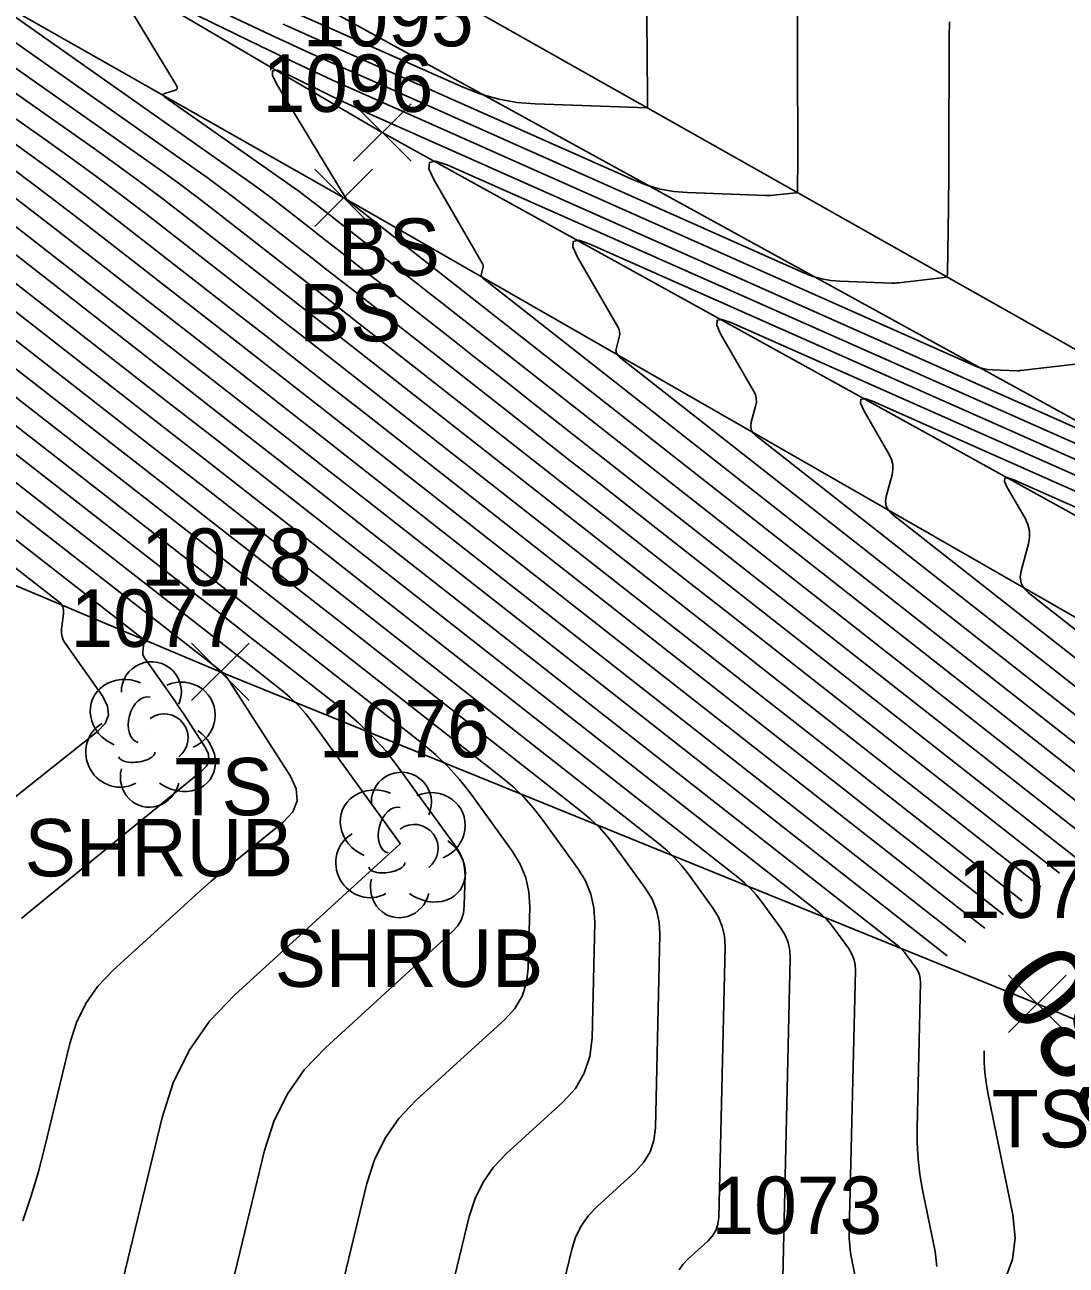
# Model space of a CAD drawing. Extents: x 1650836 to 1652450, y 332578 to 333908.
# Drawn here: x 1651878.29 to 1651914.59, y 332846.53 to 332889.77 of the extents above; entities that cross this region are included whole.
import ezdxf

# ---------------------------------------------------------------- set-up
doc = ezdxf.new("R2010")
doc.units = 0
for name, color, linetype in [('L_A', 7, 'Continuous'), ('L_I', 7, 'Continuous'), ('L_TIC', 7, 'Continuous'), ('LELB', 7, 'Continuous'), ('LSH', 7, 'Continuous'), ('LSOGCMA', 7, 'Continuous'), ('LSOGCMA_T', 7, 'Continuous'), ('LSOGCMI', 7, 'Continuous'), ('PET', 7, 'Continuous')]:
    doc.layers.add(name, color=color, linetype=linetype)

msp = doc.modelspace()

# ---------------------------------------------------------------- linework, layer by layer
at = {"layer": 'L_TIC'}
for points in [[(1651889.753, 332885.019), (1651891.753, 332887.019)], [(1651891.753, 332885.019), (1651889.753, 332887.019)], [(1651888.406, 332882.733), (1651890.406, 332884.733)], [(1651890.406, 332882.733), (1651888.406, 332884.733)], [(1651884.106, 332866.214), (1651886.106, 332868.214)], [(1651886.106, 332866.214), (1651884.106, 332868.214)], [(1651912.583, 332854.638), (1651914.583, 332856.638)], [(1651914.583, 332854.638), (1651912.583, 332856.638)]]:
    msp.add_lwpolyline(points, dxfattribs=at)
at = {"layer": 'LELB'}
for points in [[(1651844.759, 332915.941), (1651880.379, 332894.976), (1651917.082, 332874.787), (1651949.824, 332853.945), (1651967.074, 332844.342), (1652000.53, 332828.254), (1652035.357, 332809.776), (1652067.23, 332793.489), (1652106.029, 332773.108), (1652143.274, 332753.324), (1652172.167, 332734.049)], [(1652048.756, 332662.461), (1652082.555, 332678.298), (1652130.366, 332703.201), (1652148.083, 332715.406), (1652159.47, 332726.367), (1652148.02, 332734.227), (1652128.413, 332739.339), (1652116.951, 332747.33), (1652106.793, 332756.875), (1652094.604, 332761.138), (1652083.802, 332764.466), (1652074.482, 332770.284), (1652065.17, 332770.428), (1652062.989, 332774.387), (1652054.537, 332784.724), (1652034.993, 332796.475), (1652025.062, 332801.1), (1652009.772, 332808.074), (1651988.967, 332816.401), (1651980.006, 332832.954), (1651960.575, 332843.477), (1651932.852, 332862.75), (1651890.753, 332886.019), (1651847.527, 332911.35)], [(1651992.104, 332790.093), (1651989.915, 332804.738), (1651988.967, 332816.401), (1651977.078, 332830.976), (1651959.162, 332840.786), (1651931.328, 332859.703), (1651889.406, 332883.733), (1651845.231, 332908.813)], [(1651981.067, 332787.388), (1651974.596, 332810.786), (1651972.976, 332830.46), (1651956.891, 332837.411), (1651913.583, 332855.638), (1651885.106, 332867.214), (1651834.429, 332888.588)]]:
    msp.add_lwpolyline(points, dxfattribs=at)
at = {"layer": 'LSH'}
for p, q in [((1651882.657, 332865.085), (1651882.657, 332865.085)), ((1651882.657, 332865.085), (1651882.657, 332865.085)), ((1651891.371, 332861.234), (1651891.371, 332861.234)), ((1651891.371, 332861.234), (1651891.371, 332861.234))]:
    msp.add_line(p, q, dxfattribs=at)
for centre in [(1651882.704, 332866.519), (1651891.418, 332862.668)]:
    msp.add_arc(centre, 1.047, 335.5272, 180.9563, dxfattribs=at)
for centre, major_axis, ratio, start_param, end_param in [((1651881.865, 332865.752), (1.21, -0.512), 0.895232, 1.570796, 4.712389), ((1651883.698, 332865.669), (-1.141, -0.483), 0.949671, 1.570796, 4.712389), ((1651882.448, 332865.543), (-0.208, -0.792), 0.645439, 3.141593, 6.283185), ((1651883.157, 332864.919), (-0.5, 0.667), 0.989748, 3.141593, 6.283185), ((1651881.574, 332864.377), (0.584, -1.042), 0.959034, 3.141593, 6.283185), ((1651883.657, 332864.252), (-1.09, 0.792), 0.841452, 1.570796, 4.712389), ((1651882.199, 332864.335), (-0.625, -0.083), 0.423636, 0, 3.141593), ((1651882.657, 332863.585), (0.265, 1.061), 0.942809, 1.570796, 4.712389), ((1651890.58, 332861.9), (1.21, -0.512), 0.895232, 1.570796, 4.712389), ((1651892.413, 332861.817), (-1.141, -0.483), 0.949671, 1.570796, 4.712389), ((1651891.163, 332861.692), (-0.208, -0.792), 0.645439, 3.141593, 6.283185), ((1651891.871, 332861.067), (-0.5, 0.667), 0.989748, 3.141593, 6.283185), ((1651890.288, 332860.525), (0.584, -1.042), 0.959034, 3.141593, 6.283185), ((1651892.372, 332860.401), (-1.09, 0.792), 0.841452, 1.570796, 4.712389), ((1651890.913, 332860.484), (-0.625, -0.083), 0.423636, 0, 3.141593), ((1651891.372, 332859.734), (0.265, 1.061), 0.942809, 1.570796, 4.712389)]:
    msp.add_ellipse(centre, major_axis=major_axis, ratio=ratio, start_param=start_param, end_param=end_param, dxfattribs=at)
at = {"layer": 'LSOGCMA'}
for points in [[(1651911.748, 332858.275), (1651911.497, 332858.472), (1651910.953, 332858.899), (1651910.409, 332859.326), (1651909.864, 332859.754), (1651909.32, 332860.181), (1651890.123, 332875.244), (1651888.907, 332876.197), (1651887.691, 332877.149), (1651886.474, 332878.099), (1651885.256, 332879.049), (1651880.382, 332882.846), (1651879.158, 332883.788), (1651877.923, 332884.715), (1651876.676, 332885.627), (1651875.419, 332886.523), (1651848.21, 332905.675)], [(1651920.349, 332861.439), (1651899.012, 332878.194), (1651898.948, 332878.258), (1651898.91, 332878.331), (1651898.897, 332878.413), (1651898.91, 332878.503), (1651899.011, 332878.881), (1651899.028, 332878.974), (1651899.025, 332879.064), (1651899.004, 332879.152), (1651898.964, 332879.238), (1651897.554, 332881.671), (1651897.391, 332882.025), (1651897.406, 332882.22), (1651897.598, 332882.256), (1651897.967, 332882.132), (1651919.159, 332872.735)], [(1651868.932, 332881.845), (1651884.308, 332869.865), (1651884.927, 332869.383), (1651885.544, 332868.9), (1651886.162, 332868.417), (1651886.779, 332867.933), (1651889.418, 332865.863), (1651889.932, 332865.43), (1651890.412, 332864.965), (1651890.859, 332864.467), (1651891.271, 332863.937), (1651893.333, 332861.094), (1651893.47, 332860.871), (1651893.566, 332860.635), (1651893.621, 332860.386), (1651893.635, 332860.125), (1651893.61, 332859.055), (1651893.58, 332858.798), (1651893.501, 332858.564), (1651893.376, 332858.351), (1651893.202, 332858.159), (1651888.769, 332854.114), (1651888.033, 332853.339), (1651887.434, 332852.483), (1651886.972, 332851.546), (1651886.647, 332850.527), (1651883.641, 332838.089)]]:
    msp.add_lwpolyline(points, dxfattribs=at)
at = {"layer": 'LSOGCMI'}
for points in [[(1651845.912, 332905.525), (1651871.913, 332887.223), (1651873.486, 332886.101), (1651875.044, 332884.961), (1651876.589, 332883.802), (1651878.12, 332882.624), (1651884.215, 332877.875), (1651885.739, 332876.687), (1651887.261, 332875.498), (1651888.782, 332874.308), (1651890.302, 332873.116), (1651910.444, 332857.312)], [(1651847.061, 332905.6), (1651873.666, 332886.873), (1651875.081, 332885.864), (1651876.484, 332884.838), (1651877.874, 332883.795), (1651879.251, 332882.735), (1651884.735, 332878.462), (1651886.106, 332877.393), (1651887.476, 332876.323), (1651888.845, 332875.252), (1651890.213, 332874.18), (1651911.096, 332857.794)], [(1651912.399, 332858.755), (1651909.768, 332860.822), (1651908.772, 332861.604), (1651907.776, 332862.385), (1651906.781, 332863.167), (1651905.785, 332863.948), (1651890.033, 332876.308), (1651888.97, 332877.141), (1651887.906, 332877.974), (1651886.841, 332878.805), (1651885.776, 332879.636), (1651881.513, 332882.958), (1651880.442, 332883.781), (1651879.362, 332884.592), (1651878.272, 332885.389), (1651877.172, 332886.173), (1651849.359, 332905.751)], [(1651851.136, 332905.867), (1651851.012, 332905.705), (1651851.086, 332905.478), (1651851.378, 332905.214), (1651878.925, 332885.824), (1651879.867, 332885.152), (1651880.801, 332884.469), (1651881.727, 332883.774), (1651882.644, 332883.069), (1651886.296, 332880.223), (1651887.209, 332879.511), (1651888.121, 332878.799), (1651889.032, 332878.086), (1651889.943, 332877.372), (1651902.25, 332867.715), (1651903.697, 332866.58), (1651905.144, 332865.444), (1651906.591, 332864.308), (1651908.038, 332863.172), (1651913.05, 332859.236)], [(1651846.352, 332902.563), (1651866.654, 332888.272), (1651868.7, 332886.813), (1651870.727, 332885.33), (1651872.736, 332883.823), (1651874.727, 332882.291), (1651882.655, 332876.114), (1651884.636, 332874.569), (1651886.616, 332873.023), (1651888.595, 332871.474), (1651890.572, 332869.924), (1651903.158, 332860.049), (1651903.379, 332859.862), (1651903.587, 332859.662), (1651903.779, 332859.447), (1651903.957, 332859.218), (1651904.641, 332858.276), (1651904.789, 332858.033), (1651904.894, 332857.777), (1651904.953, 332857.507), (1651904.969, 332857.223), (1651904.684, 332845.065)], [(1651857.738, 332901.621), (1651880.678, 332885.474), (1651881.462, 332884.915), (1651882.24, 332884.346), (1651883.011, 332883.767), (1651883.775, 332883.18), (1651886.816, 332880.81), (1651887.576, 332880.218), (1651888.336, 332879.624), (1651889.095, 332879.03), (1651889.853, 332878.435), (1651898.968, 332871.284), (1651900.74, 332869.893), (1651902.512, 332868.503), (1651904.283, 332867.112), (1651906.055, 332865.721), (1651913.701, 332859.717)], [(1651914.352, 332860.197), (1651902.711, 332869.338), (1651901.295, 332870.45), (1651899.88, 332871.561), (1651898.464, 332872.673), (1651897.048, 332873.784), (1651889.763, 332879.499), (1651889.157, 332879.975), (1651888.55, 332880.449), (1651887.943, 332880.924), (1651887.336, 332881.397), (1651884.906, 332883.291), (1651884.295, 332883.761), (1651883.679, 332884.223), (1651883.058, 332884.677), (1651882.431, 332885.124), (1651864.098, 332898.029)], [(1651886.698, 332890.648), (1651893.59, 332887.584), (1651894.192, 332887.349), (1651894.808, 332887.175), (1651895.438, 332887.061), (1651896.082, 332887.008), (1651899.985, 332886.869), (1651899.99, 332886.869), (1651899.996, 332886.87), (1651899.997, 332886.871), (1651899.997, 332886.873), (1651899.997, 332886.965), (1651899.997, 332886.997), (1651899.997, 332887.028), (1651899.995, 332887.159), (1651899.994, 332887.213), (1651899.994, 332887.267), (1651899.925, 332895.585)], [(1651905.217, 332894.718), (1651905.219, 332889.324), (1651905.219, 332888.95), (1651905.22, 332888.576), (1651905.221, 332888.202), (1651905.223, 332887.829), (1651905.232, 332886.001), (1651905.233, 332885.793), (1651905.233, 332885.585), (1651905.232, 332885.377), (1651905.231, 332885.169), (1651905.221, 332883.962), (1651905.219, 332883.944), (1651905.211, 332883.93), (1651905.198, 332883.921), (1651905.18, 332883.916), (1651904.495, 332883.837), (1651904.401, 332883.828), (1651904.307, 332883.823), (1651904.213, 332883.821), (1651904.119, 332883.822), (1651901.389, 332883.919), (1651900.908, 332883.959), (1651900.437, 332884.044), (1651899.977, 332884.174), (1651899.527, 332884.35), (1651889.172, 332888.954), (1651887.301, 332889.796)], [(1651870.458, 332894.436), (1651884.184, 332884.775), (1651884.653, 332884.44), (1651885.118, 332884.1), (1651885.579, 332883.754), (1651886.036, 332883.402), (1651887.856, 332881.984), (1651888.311, 332881.63), (1651888.765, 332881.275), (1651889.22, 332880.919), (1651889.673, 332880.563), (1651895.127, 332876.284), (1651896.187, 332875.452), (1651897.247, 332874.62), (1651898.307, 332873.788), (1651899.367, 332872.956), (1651917.33, 332858.851)], [(1651876.818, 332890.843), (1651885.936, 332884.425), (1651886.248, 332884.203), (1651886.557, 332883.977), (1651886.864, 332883.747), (1651887.167, 332883.513), (1651888.376, 332882.571), (1651888.678, 332882.336), (1651888.98, 332882.1), (1651889.282, 332881.864), (1651889.584, 332881.627), (1651893.207, 332878.784), (1651893.911, 332878.232), (1651894.615, 332877.679), (1651895.319, 332877.126), (1651896.023, 332876.573), (1651917.934, 332859.368)], [(1651882.25, 332891.108), (1651886.488, 332889.037), (1651887.377, 332888.608), (1651888.269, 332888.187), (1651889.165, 332887.774), (1651890.065, 332887.369), (1651911.4, 332877.882), (1651911.546, 332877.825), (1651911.695, 332877.783), (1651911.847, 332877.755), (1651912.003, 332877.742), (1651912.886, 332877.711), (1651912.917, 332877.71), (1651912.947, 332877.711), (1651912.978, 332877.713), (1651913.008, 332877.716), (1651915.404, 332877.993)], [(1651918.538, 332859.886), (1651892.68, 332880.191), (1651892.331, 332880.464), (1651891.983, 332880.738), (1651891.635, 332881.011), (1651891.286, 332881.285), (1651889.494, 332882.691), (1651889.344, 332882.808), (1651889.195, 332882.925), (1651889.046, 332883.042), (1651888.896, 332883.158), (1651888.298, 332883.624), (1651888.148, 332883.74), (1651887.997, 332883.853), (1651887.844, 332883.965), (1651887.689, 332884.075), (1651883.178, 332887.251), (1651883.131, 332887.294), (1651883.118, 332887.331), (1651883.142, 332887.362), (1651883.201, 332887.387), (1651883.51, 332887.475), (1651883.573, 332887.503), (1651883.606, 332887.542), (1651883.608, 332887.593), (1651883.582, 332887.656), (1651881.792, 332890.607)], [(1651910.516, 332889.866), (1651910.514, 332889.359), (1651910.499, 332885.022), (1651910.497, 332884.617), (1651910.494, 332884.212), (1651910.489, 332883.807), (1651910.484, 332883.402), (1651910.447, 332881.082), (1651910.439, 332881.033), (1651910.418, 332880.997), (1651910.384, 332880.972), (1651910.336, 332880.96), (1651908.752, 332880.777), (1651908.689, 332880.771), (1651908.627, 332880.767), (1651908.565, 332880.766), (1651908.503, 332880.767), (1651906.696, 332880.831), (1651906.378, 332880.857), (1651906.066, 332880.914), (1651905.761, 332881), (1651905.464, 332881.116), (1651889.673, 332888.137), (1651888.261, 332888.773), (1651886.854, 332889.421), (1651885.454, 332890.082)], [(1651915.292, 332875.557), (1651890.457, 332886.6), (1651890.069, 332886.775), (1651889.684, 332886.952), (1651889.299, 332887.134), (1651888.917, 332887.319), (1651887.39, 332888.065), (1651887.083, 332888.182), (1651886.927, 332888.163), (1651886.922, 332888.006), (1651887.067, 332887.711), (1651889.425, 332883.821), (1651889.434, 332883.808), (1651889.442, 332883.794), (1651889.45, 332883.781), (1651889.458, 332883.767), (1651889.504, 332883.686), (1651889.505, 332883.684), (1651889.504, 332883.678), (1651889.505, 332883.676), (1651919.142, 332860.404)], [(1651861.542, 332886.484), (1651862.099, 332886.077), (1651864.677, 332884.143), (1651867.233, 332882.177), (1651884.698, 332868.569), (1651885.014, 332868.322), (1651885.33, 332868.076), (1651885.646, 332867.829), (1651885.961, 332867.582), (1651887.222, 332866.592), (1651887.527, 332866.335), (1651887.812, 332866.059), (1651888.077, 332865.764), (1651888.323, 332865.449), (1651891.379, 332861.233), (1651891.38, 332861.229), (1651891.38, 332861.224), (1651891.379, 332861.222), (1651885.613, 332855.96), (1651884.733, 332855.034), (1651884.018, 332854.012), (1651883.466, 332852.892), (1651883.079, 332851.676), (1651881.536, 332845.295)], [(1651919.745, 332860.921), (1651894.259, 332880.935), (1651894.226, 332880.967), (1651894.207, 332881.004), (1651894.2, 332881.046), (1651894.207, 332881.091), (1651894.258, 332881.282), (1651894.266, 332881.329), (1651894.265, 332881.374), (1651894.254, 332881.419), (1651894.234, 332881.462), (1651892.562, 332884.347), (1651892.376, 332884.751), (1651892.393, 332884.973), (1651892.612, 332885.014), (1651893.034, 332884.873), (1651918.142, 332873.739)], [(1651875.584, 332860.975), (1651880.831, 332865.138), (1651881.09, 332865.411), (1651881.206, 332865.705), (1651881.178, 332866.02), (1651881.006, 332866.356), (1651879.697, 332868.21), (1651879.631, 332868.323), (1651879.589, 332868.442), (1651879.571, 332868.568), (1651879.576, 332868.699), (1651879.644, 332869.235), (1651879.646, 332869.363), (1651879.617, 332869.478), (1651879.556, 332869.58), (1651879.465, 332869.669), (1651862.133, 332883.174)], [(1651863.833, 332882.841), (1651882.351, 332868.413), (1651882.395, 332868.37), (1651882.425, 332868.32), (1651882.439, 332868.264), (1651882.438, 332868.201), (1651882.405, 332867.939), (1651882.402, 332867.875), (1651882.411, 332867.814), (1651882.432, 332867.756), (1651882.464, 332867.7), (1651883.36, 332866.431), (1651883.519, 332866.203), (1651883.676, 332865.972), (1651883.831, 332865.74), (1651883.983, 332865.507), (1651884.586, 332864.568), (1651884.691, 332864.341), (1651884.704, 332864.129), (1651884.625, 332863.93), (1651884.455, 332863.747), (1651878.54, 332858.922), (1651878.356, 332858.77), (1651878.173, 332858.614)], [(1651878.219, 332848.077), (1651878.501, 332848.913), (1651878.753, 332849.757), (1651878.975, 332850.612), (1651879.858, 332854.265), (1651880.088, 332854.987), (1651880.415, 332855.651), (1651880.84, 332856.258), (1651881.361, 332856.807), (1651883.984, 332859.2), (1651884.386, 332859.562), (1651884.793, 332859.918), (1651885.205, 332860.268), (1651885.621, 332860.613), (1651887.298, 332861.98), (1651887.628, 332862.336), (1651887.78, 332862.72), (1651887.754, 332863.133), (1651887.551, 332863.574), (1651885.414, 332866.899), (1651885.396, 332866.927), (1651885.377, 332866.954), (1651885.359, 332866.98), (1651885.34, 332867.007), (1651885.245, 332867.138), (1651885.235, 332867.151), (1651885.223, 332867.164), (1651885.211, 332867.176), (1651885.198, 332867.187), (1651885.129, 332867.241), (1651885.088, 332867.273), (1651865.533, 332882.509)], [(1651901.097, 332846.368), (1651901.23, 332846.558), (1651901.394, 332846.73), (1651902.108, 332847.382), (1651902.265, 332847.555), (1651902.379, 332847.747), (1651902.45, 332847.96), (1651902.477, 332848.192), (1651902.698, 332857.64), (1651902.679, 332857.999), (1651902.603, 332858.341), (1651902.471, 332858.665), (1651902.284, 332858.971), (1651901.42, 332860.162), (1651901.195, 332860.451), (1651900.952, 332860.722), (1651900.69, 332860.976), (1651900.41, 332861.212), (1651890.05, 332869.34), (1651888.227, 332870.77), (1651886.402, 332872.198), (1651884.576, 332873.624), (1651882.748, 332875.049), (1651873.596, 332882.18)], [(1651875.858, 332882.402), (1651883.175, 332876.701), (1651885.004, 332875.275), (1651886.831, 332873.848), (1651888.657, 332872.419), (1651890.482, 332870.988), (1651905.906, 332858.886), (1651906.069, 332858.749), (1651906.222, 332858.601), (1651906.363, 332858.443), (1651906.495, 332858.274), (1651906.998, 332857.58), (1651907.107, 332857.402), (1651907.184, 332857.213), (1651907.228, 332857.014), (1651907.239, 332856.805), (1651907.027, 332847.717), (1651907.028, 332847.465), (1651907.043, 332847.214), (1651907.072, 332846.964), (1651907.116, 332846.716), (1651907.318, 332845.725)], [(1651876.989, 332882.513), (1651883.695, 332877.288), (1651885.371, 332875.981), (1651887.046, 332874.673), (1651888.72, 332873.363), (1651890.392, 332872.052), (1651908.654, 332857.723), (1651908.759, 332857.635), (1651908.857, 332857.54), (1651908.948, 332857.439), (1651909.032, 332857.331), (1651909.355, 332856.885), (1651909.425, 332856.77), (1651909.474, 332856.649), (1651909.503, 332856.521), (1651909.51, 332856.387), (1651909.391, 332851.322), (1651909.394, 332850.776), (1651909.427, 332850.233), (1651909.49, 332849.692), (1651909.584, 332849.154), (1651910.021, 332847.009), (1651910.074, 332846.486)], [(1651870.204, 332881.847), (1651883.918, 332871.161), (1651884.839, 332870.443), (1651885.759, 332869.725), (1651886.678, 332869.005), (1651887.597, 332868.285), (1651892.166, 332864.7), (1651892.621, 332864.316), (1651893.047, 332863.904), (1651893.443, 332863.463), (1651893.809, 332862.994), (1651895.287, 332860.954), (1651895.56, 332860.509), (1651895.751, 332860.038), (1651895.861, 332859.542), (1651895.889, 332859.021), (1651895.839, 332856.885), (1651895.779, 332856.373), (1651895.623, 332855.904), (1651895.372, 332855.479), (1651895.025, 332855.097), (1651891.925, 332852.268), (1651891.332, 332851.644), (1651890.85, 332850.954), (1651890.478, 332850.199), (1651890.216, 332849.379), (1651885.746, 332830.882)], [(1651871.334, 332881.958), (1651883.528, 332872.457), (1651884.751, 332871.504), (1651885.973, 332870.549), (1651887.194, 332869.593), (1651888.414, 332868.637), (1651894.914, 332863.537), (1651895.311, 332863.203), (1651895.682, 332862.843), (1651896.027, 332862.459), (1651896.346, 332862.05), (1651897.569, 332860.362), (1651897.836, 332859.928), (1651898.022, 332859.468), (1651898.129, 332858.985), (1651898.157, 332858.476), (1651898.063, 332854.445), (1651897.987, 332853.807), (1651897.793, 332853.222), (1651897.48, 332852.692), (1651897.048, 332852.217), (1651895.081, 332850.422), (1651894.631, 332849.948), (1651894.266, 332849.425), (1651893.983, 332848.853), (1651893.785, 332848.23), (1651887.96, 332824.128)], [(1651893.889, 332832.748), (1651897.354, 332847.082), (1651897.489, 332847.506), (1651897.681, 332847.896), (1651897.931, 332848.253), (1651898.237, 332848.576), (1651899.578, 332849.799), (1651899.873, 332850.124), (1651900.086, 332850.485), (1651900.219, 332850.883), (1651900.27, 332851.318), (1651900.428, 332858.058), (1651900.404, 332858.492), (1651900.313, 332858.905), (1651900.154, 332859.296), (1651899.927, 332859.666), (1651898.883, 332861.106), (1651898.611, 332861.455), (1651898.317, 332861.783), (1651898, 332862.089), (1651897.662, 332862.374), (1651889.232, 332868.988), (1651887.71, 332870.182), (1651886.187, 332871.373), (1651884.663, 332872.564), (1651883.138, 332873.753), (1651872.465, 332882.069)], [(1651920.175, 332871.731), (1651902.901, 332879.391), (1651902.583, 332879.497), (1651902.418, 332879.467), (1651902.406, 332879.299), (1651902.545, 332878.995), (1651903.694, 332877.014), (1651903.754, 332876.886), (1651903.785, 332876.754), (1651903.789, 332876.619), (1651903.765, 332876.479), (1651903.612, 332875.915), (1651903.593, 332875.781), (1651903.613, 332875.659), (1651903.67, 332875.549), (1651903.766, 332875.453), (1651920.953, 332861.957)], [(1651937.731, 332848.912), (1651930.898, 332854.802), (1651928.687, 332856.686), (1651926.454, 332858.545), (1651924.2, 332860.378), (1651921.926, 332862.185), (1651908.52, 332872.712), (1651908.392, 332872.84), (1651908.316, 332872.986), (1651908.29, 332873.148), (1651908.315, 332873.327), (1651908.518, 332874.078), (1651908.55, 332874.263), (1651908.545, 332874.444), (1651908.503, 332874.619), (1651908.424, 332874.79), (1651907.537, 332876.32), (1651907.421, 332876.574), (1651907.431, 332876.713), (1651907.569, 332876.739), (1651907.834, 332876.65), (1651921.192, 332870.727), (1651922.452, 332870.151)], [(1651922.356, 332869.658), (1651912.767, 332873.909), (1651912.554, 332873.98), (1651912.444, 332873.96), (1651912.435, 332873.848), (1651912.529, 332873.644), (1651913.154, 332872.566), (1651913.253, 332872.353), (1651913.305, 332872.134), (1651913.311, 332871.908), (1651913.271, 332871.677), (1651913.018, 332870.74), (1651912.987, 332870.516), (1651913.019, 332870.313), (1651913.114, 332870.131), (1651913.273, 332869.971), (1651923.828, 332861.683), (1651925.643, 332860.241), (1651927.44, 332858.779), (1651929.221, 332857.297), (1651930.985, 332855.794), (1651938.671, 332849.169)], [(1651911.735, 332854.003), (1651911.734, 332853.955), (1651911.735, 332853.6), (1651911.757, 332853.247), (1651911.798, 332852.895), (1651911.859, 332852.545), (1651912.725, 332848.293), (1651912.806, 332847.489), (1651912.714, 332846.727), (1651912.448, 332846.007), (1651912.008, 332845.329), (1651909.627, 332842.355), (1651909.046, 332841.648), (1651908.449, 332840.955), (1651907.835, 332840.277), (1651907.204, 332839.614), (1651902.766, 332835.057), (1651901.839, 332834.058), (1651900.965, 332833.017), (1651900.142, 332831.935), (1651899.372, 332830.811), (1651892.418, 332820.116)]]:
    msp.add_lwpolyline(points, dxfattribs=at)
at = {"layer": 'PET'}
msp.add_lwpolyline([(1651764.546, 332972.615), (1651784.506, 332958.597), (1651809.702, 332941.927), (1651846.26, 332918.158), (1651881.765, 332897.162), (1651918.116, 332876.642), (1651951.432, 332858.415), (1651975.296, 332845.48), (1652002.223, 332831.337), (1652037.173, 332813.417), (1652069.296, 332796.636), (1652107.428, 332776.545), (1652145.079, 332756.921), (1652175.234, 332740.226), (1652190.754, 332731.861), (1652206.573, 332723.523), (1652239.422, 332706.921), (1652282.404, 332684.366), (1652332.494, 332658.525), (1652365.542, 332641.171), (1652388.914, 332629.021)], dxfattribs=at)

# ---------------------------------------------------------------- texts
at = {"layer": 'L_A'}
for s, p in [('BS', (1651889.194, 332881.019)), ('BS', (1651887.847, 332878.733)), ('TS', (1651883.516, 332862.214)), ('SHRUB', (1651878.287, 332860.085)), ('SHRUB', (1651887.001, 332856.234)), ('TS', (1651911.993, 332850.638))]:
    msp.add_text(s, height=2, dxfattribs=at).set_placement(p)
at = {"layer": 'L_I'}
for s, p in [('1095', (1651887.982, 332889.019)), ('1096', (1651886.579, 332886.733)), ('1078', (1651882.335, 332870.214)), ('1077', (1651879.885, 332868.085)), ('1076', (1651888.545, 332864.234)), ('1075', (1651910.812, 332858.638)), ('1073', (1651902.225, 332847.622))]:
    msp.add_text(s, height=2, dxfattribs=at).set_placement(p)
at = {"layer": 'LSOGCMA_T'}
msp.add_text('830', height=3, rotation=126.4323, dxfattribs=at).set_placement((1651918.341, 332852.63))

doc.saveas('drawing.dxf')
